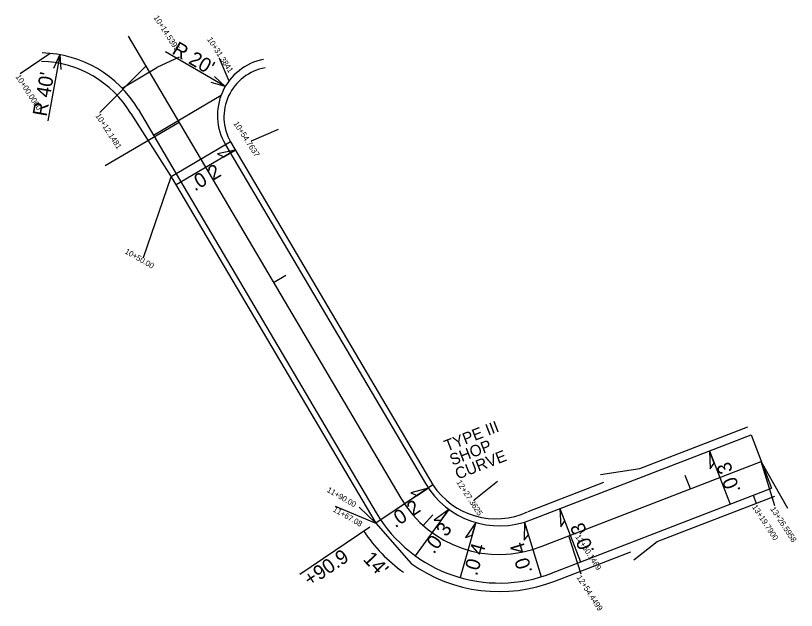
# Model space of a CAD drawing. Extents: x 757566 to 757839, y 594520 to 594729.
import ezdxf

# ---------------------------------------------------------------- set-up
doc = ezdxf.new("R2010")
doc.units = 0
for name, color, linetype in [('COGO Default Point Elevation', 7, 'Continuous'), ('Default', 7, 'Continuous'), ('Prop Dimension', 7, 'Continuous'), ('Prop EOT', 7, 'Continuous'), ('Prop Guardrail', 7, 'Continuous'), ('Prop Guardrail Shop Curved', 7, 'Continuous'), ('Prop Horizontal Alignment', 7, 'Continuous'), ('Prop Horizontal Alignment Tick Small', 7, 'Continuous'), ('Prop Roadway Bridge', 7, 'Continuous'), ('Prop Superelevation  Arrow CELL', 7, 'Continuous'), ('Scratch_Level_2', 7, 'Continuous')]:
    doc.layers.add(name, color=color, linetype=linetype)

msp = doc.modelspace()

# ---------------------------------------------------------------- linework, layer by layer
at = {"layer": 'COGO Default Point Elevation'}
for points in [[(757567.31, 594708.23), (757577.79, 594715.4)], [(757622.88, 594713.98), (757615.09, 594710.35)], [(757636.89, 594713.6), (757640.31, 594705.66)], [(757595.23, 594694.61), (757611.26, 594710.87)], [(757648.14, 594684.67), (757657.67, 594688.75)], [(757610.48, 594643.89), (757620.15, 594672.17)], [(757835.66, 594556.09), (757826.37, 594572.61)], [(757831.12, 594557.05), (757826.37, 594572.61)], [(757726.05, 594559.16), (757734.19, 594565.7)], [(757824.74, 594557.72), (757823.64, 594560.82)], [(757677.46, 594556.98), (757691.61, 594550.94)], [(757685.83, 594556.6), (757691.61, 594550.94)], [(757762.94, 594547.28), (757764.41, 594548.6)], [(757763.38, 594533.09), (757759.1, 594546.55)]]:
    msp.add_lwpolyline(points, dxfattribs=at)
at = {"layer": 'Default'}
for p, q in [((757602.94, 594703.19), (757615.09, 594710.35)), ((757613.89, 594686.73), (757637.56, 594700.68))]:
    msp.add_line(p, q, dxfattribs=at)
at = {"layer": 'Prop Dimension'}
for p, q in [((757638.99, 594703.68), (757618.18, 594715.82)), ((757581.17, 594714.85), (757577.02, 594691.77))]:
    msp.add_line(p, q, dxfattribs=at)
for points in [[(757579.05, 594710.15), (757581.17, 594714.85), (757581.51, 594709.7)], [(757635.3, 594707.28), (757638.99, 594703.68), (757634.04, 594705.12)]]:
    msp.add_lwpolyline(points, dxfattribs=at)
at = {"layer": 'Prop EOT'}
for p, q in [((757608.55, 594695.79), (757621.87, 594673.18)), ((757639.04, 594683.45), (757639.1, 594683.34)), ((757639.1, 594683.34), (757708.98, 594564.8)), ((757621.87, 594673.18), (757691.75, 594554.65)), ((757745.81, 594552.12), (757822.76, 594581.93)), ((757822.76, 594581.93), (757829.98, 594563.28)), ((757753.08, 594533.49), (757829.98, 594563.28))]:
    msp.add_line(p, q, dxfattribs=at)
for centre, radius, start, end in [((757574.09, 594675.48), 40, 30.5186, 88.6356), ((757656.27, 594693.61), 20, 101.1746, 210.5186), ((757734.82, 594580.04), 30, 210.5186, 291.4779), ((757734.82, 594580.04), 50, 210.5186, 291.4779)]:
    msp.add_arc(centre, radius, start, end, dxfattribs=at)
at = {"layer": 'Prop Guardrail'}
for p, q in [((757605.96, 594694.27), (757620.15, 594672.17)), ((757622.87, 594691.18), (757597.02, 594675.95)), ((757771.24, 594565.2), (757744.71, 594554.91)), ((757691.61, 594550.94), (757704.01, 594536.92)), ((757754.23, 594530.72), (757780.76, 594540.98))]:
    msp.add_line(p, q, dxfattribs=at)
for centre, radius, start, end in [((757574.09, 594675.48), 37, 30.5186, 88.8798), ((757656.09, 594693.01), 17.55, 100.2217, 209.5657), ((757733.67, 594579.06), 26.55, 213.5979, 294.5572), ((757734.82, 594580.04), 53, 234.451, 291.4779)]:
    msp.add_arc(centre, radius, start, end, dxfattribs=at)
at = {"layer": 'Prop Horizontal Alignment'}
for p, q in [((757605.1, 594721.34), (757700.36, 594559.72)), ((757749.47, 594542.81), (757826.37, 594572.61))]:
    msp.add_line(p, q, dxfattribs=at)
msp.add_arc((757734.82, 594580.04), 40, 210.5186, 291.4779, dxfattribs=at)
at = {"layer": 'Prop Horizontal Alignment Tick Small'}
for p, q in [((757655.88, 594635.19), (757660.18, 594637.73)), ((757801.57, 594563), (757799.77, 594567.66)), ((757708.2, 594550.18), (757711.53, 594553.91))]:
    msp.add_line(p, q, dxfattribs=at)
at = {"layer": 'Prop Roadway Bridge'}
for p, q in [((757640.82, 594684.36), (757620.15, 594672.17)), ((757640.82, 594684.36), (757711.55, 594564.37)), ((757620.15, 594672.17), (757691.61, 594550.94)), ((757711.55, 594564.37), (757691.61, 594550.94))]:
    msp.add_line(p, q, dxfattribs=at)
at = {"layer": 'Prop Superelevation  Arrow CELL'}
for p, q in [((757642.53, 594681.47), (757621.85, 594669.28)), ((757808.22, 594576.3), (757815.44, 594557.65)), ((757709.94, 594563.28), (757693.35, 594552.11)), ((757717.19, 594555.76), (757705.44, 594539.58)), ((757756, 594556.07), (757763.22, 594537.42)), ((757689.6, 594549.59), (757665.05, 594533.05)), ((757726.58, 594551.19), (757721.09, 594531.96)), ((757743.6, 594551.35), (757749.45, 594532.22))]:
    msp.add_line(p, q, dxfattribs=at)
for points in [[(757642.53, 594681.47), (757636.33, 594680.18), (757638.53, 594679.15)], [(757808.22, 594576.3), (757808.52, 594569.98), (757809.89, 594571.99)], [(757709.94, 594563.28), (757703.84, 594561.59), (757706.1, 594560.7)], [(757717.19, 594555.76), (757712.05, 594552.08), (757714.47, 594552.02)], [(757756, 594556.07), (757756.3, 594549.75), (757757.67, 594551.76)], [(757726.58, 594551.19), (757723.01, 594545.97), (757725.31, 594546.74)], [(757743.6, 594551.35), (757743.44, 594545.03), (757744.95, 594546.93)]]:
    msp.add_lwpolyline(points, close=True, dxfattribs=at)
msp.add_arc((757734.82, 594580.04), 57.12, 213.9545, 234.0081, dxfattribs=at)
at = {"layer": 'Scratch_Level_2'}
for p, q in [((757783.92, 594570.1), (757821.68, 594584.73)), ((757770.15, 594568), (757783.92, 594570.1)), ((757789.94, 594544.55), (757831.07, 594560.48)), ((757781.84, 594538.18), (757789.94, 594544.55))]:
    msp.add_line(p, q, dxfattribs=at)

# ---------------------------------------------------------------- texts
at = {"layer": 'COGO Default Point Elevation'}
for s, rotation, p in [('10+14.5395', 303.0183, (757613.88, 594727.83)), ('10+31.3841', 303.0183, (757632.59, 594720.21)), ('10+00.0000', 303.0183, (757565.63, 594707.14)), ('10+12.1481', 303.0183, (757593.55, 594693.52)), ('10+54.7637', 303.0183, (757641.79, 594690.77)), ('10+50.00', 330.1, (757603.7, 594645.48)), ('12+27.3625', 303.0183, (757719.7, 594565.26)), ('11+90.00', 330.1, (757674.34, 594562.05)), ('11+67.08', 330.1, (757676.46, 594555.24)), ('13+19.7900', 303.0183, (757823.06, 594556.63)), ('13+26.5958', 303.0183, (757829.44, 594555.96)), ('12+60.1469', 303.0183, (757761.26, 594546.19)), ('12+54.4499', 303.0183, (757761.7, 594532))]:
    msp.add_text(s, height=2, rotation=rotation, dxfattribs=at).set_placement(p)
at = {"layer": 'Prop Dimension'}
for s, rotation, p in [("R 20'", 329.7432, (757620.06, 594715.39)), ("R 40'", 79.8064, (757576.54, 594693.04))]:
    msp.add_text(s, height=5, rotation=rotation, dxfattribs=at).set_placement(p)
at = {"layer": 'Prop Guardrail Shop Curved'}
for s, p in [('TYPE III', (757716.48, 594575.97)), ('SHOP', (757718.38, 594571.08)), ('CURVE', (757720.27, 594566.19))]:
    msp.add_text(s, height=4, rotation=21.176, dxfattribs=at).set_placement(p)
at = {"layer": 'Prop Superelevation  Arrow CELL'}
for s, rotation, p in [('.0 2', 30.5186, (757628.39, 594666.98)), ('.0 3', 111.176, (757819.21, 594562.43)), ('.0 2', 33.9545, (757698.45, 594549.16)), ('.0 3', 54.0081, (757711.94, 594539.94)), ('.0 3', 111.176, (757768.09, 594541.22)), ('.0 4', 107.0067, (757746.4, 594534.06)), ('+90.9', 33.9545, (757668.61, 594528.63)), ('.0 4', 74.0616, (757726.99, 594532.35)), ("14'", 313.9813, (757686.89, 594538.17))]:
    msp.add_text(s, height=5, rotation=rotation, dxfattribs=at).set_placement(p)

doc.saveas('drawing.dxf')
